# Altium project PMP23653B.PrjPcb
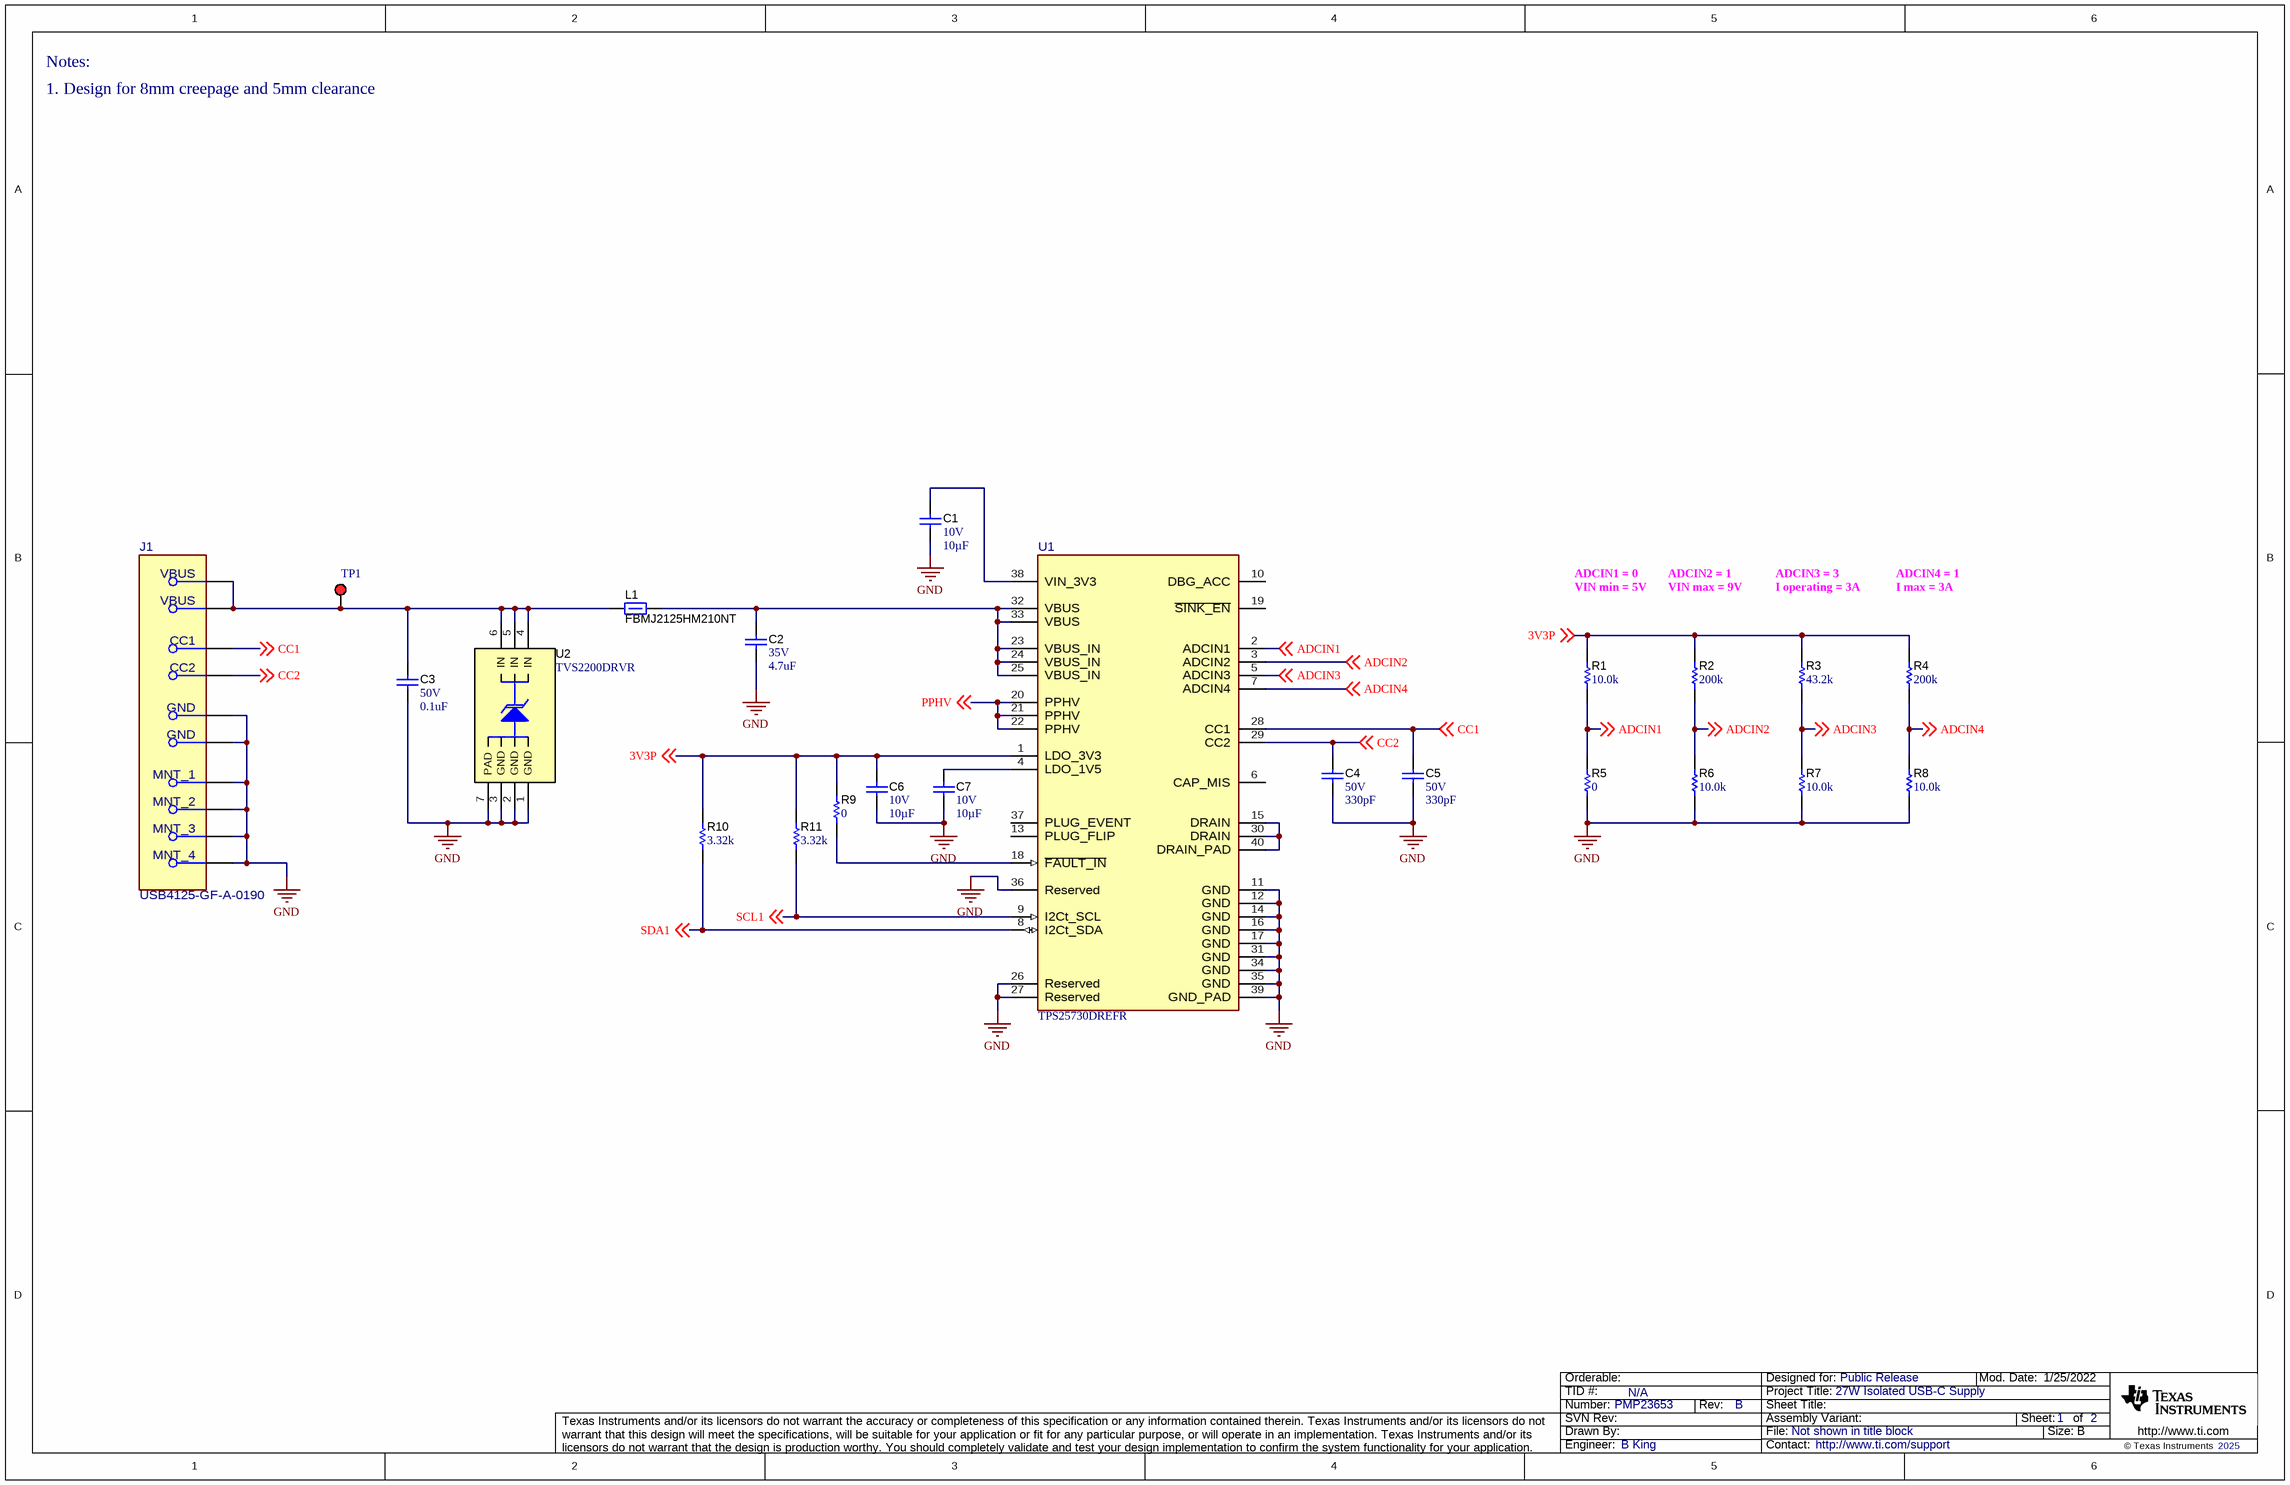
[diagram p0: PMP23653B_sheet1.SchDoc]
CopyrightYear: 2025; PCB_Layout: B King; PCB_Rev: B; PRJ_Customer: Public Release; PRJ_Engineer: B King; PRJ_Number: PMP23653; PRJ_Title: 27W Isolated USB-C Supply; SCH_Rev: B; TechSupport: http://www.ti.com/support; TID: N/A
2 sheets, 90 parts. Net scope: global (net labels, ports and power ports of the same name join across sheets).
Board file: PMP23653B.PcbDoc
Sheets:
  PMP23653B_sheet1.SchDoc
  PMP23653B_sheet2.SchDoc

## Sheet PMP23653B_sheet1.SchDoc
size 431 x 279 mm; Date: Not shown in title block; ApprovedBy: Not shown in title block; CheckedBy: Not shown in title block; Author: Not shown in title block; CompanyName: Not shown in title block; Engineer: Not shown in title block; Organization: Not shown in title block; Address1: Not shown in title block; Address2: Not shown in title block; Address3: Not shown in title block; Address4: Not shown in title block; DocumentNumber: 2; Revision: Use project parameter SCH_Rev; SheetNumber: 1; SheetTotal: 2; PageSetup: Record=PageOptions¦CenterHorizontal=True¦CenterVertical=True¦PrintScale=1.00¦XCorrection=1.00¦YCorrection=1.00¦PrintKind=0¦BorderSize=5000000¦LeftOffset=0¦BottomOffset=0¦Orientation=2¦PaperLength=1000¦PaperWidth=1000¦Scale=100¦PaperSource=15¦PrintQuality=600¦MediaType=1¦DitherType=10¦PaperKind=Letter¦PrintScaleMode=1

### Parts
C1  VDC_V: 10V  ValueDisplayed: 10µF  [0402_070]  (hidden comment: GRM155R61A106ME44)
C2  VDC_V: 35V  ValueDisplayed: 4.7uF  [0603S]  (hidden comment: GRM188R6YA475KE15D)
C3  VDC_V: 50V  ValueDisplayed: 0.1uF  [0402S]  (hidden comment: C1005X7R1H104K050BB)
C4  VDC_V: 50V  ValueDisplayed: 330pF  [0402S]  (hidden comment: GRM1555C1H331FA01J)
C5  VDC_V: 50V  ValueDisplayed: 330pF  [0402S]  (hidden comment: GRM1555C1H331FA01J)
C6  VDC_V: 10V  ValueDisplayed: 10µF  [0402_070]  (hidden comment: GRM155R61A106ME44)
C7  VDC_V: 10V  ValueDisplayed: 10µF  [0402_070]  (hidden comment: GRM155R61A106ME44)
J1  USB4125-GF-A-0190  [FP-USB4125-GF-A-0190_CONN_USB-MFG]
L1  FBMJ2125HM210NT  [0805_HV1]
R1  ValueDisplayed: 10.0k  [0402S]  (hidden comment: CRCW040210K0FKED)
R2  ValueDisplayed: 200k  [0402S]  (hidden comment: CRCW0402200KFKED)
R3  ValueDisplayed: 43.2k  [0402S]  (hidden comment: CRCW040243K2FKED)
R4  ValueDisplayed: 200k  [0402S]  (hidden comment: CRCW0402200KFKED)
R5  ValueDisplayed: 0  [0402S]  (hidden comment: CRCW04020000Z0ED)
R6  ValueDisplayed: 10.0k  [0402S]  (hidden comment: CRCW040210K0FKED)
R7  ValueDisplayed: 10.0k  [0402S]  (hidden comment: CRCW040210K0FKED)
R8  ValueDisplayed: 10.0k  [0402S]  (hidden comment: CRCW040210K0FKED)
R9  ValueDisplayed: 0  [0402S]  (hidden comment: CRCW04020000Z0ED)
R10  ValueDisplayed: 3.32k  [0402S]  (hidden comment: CRCW04023K32FKED)
R11  ValueDisplayed: 3.32k  [0402S]  (hidden comment: CRCW04023K32FKED)
TP1  5000  [Keystone5000]  (value not drawn)
U1  TPS25730DREFR  [REF0038A-MFG]
U2  TVS2200DRVR  [DRV0006A]

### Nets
GND: C1.1 C2.2 C3.2 C4.1 C5.1 C6.1 C7.1 J1.1(MNT_1) J1.2(MNT_2) J1.3(MNT_3) J1.4(MNT_4) J1.A12(GND) J1.B12(GND) R5.1 R6.2 R7.2 R8.2 U1.11(GND) U1.12(GND) U1.14(GND) U1.16(GND) U1.17(GND) U1.26(Reserved) U1.27(Reserved) U1.31(GND) U1.34(GND) U1.35(GND) U1.36(Reserved) U1.39(GND_PAD) U2.1(GND) U2.2(GND) U2.3(GND) U2.7(PAD)
3V3P: C6.2 R1.1 R2.2 R3.2 R4.2 R9.2 R10.2 R11.2 U1.1(LDO_3V3) ; off-sheet 3V3P
ADCIN1: R1.2 R5.2 U1.2(ADCIN1) ; off-sheet ADCIN1
ADCIN2: R2.1 R6.1 U1.3(ADCIN2) ; off-sheet ADCIN2
ADCIN3: R3.1 R7.1 U1.5(ADCIN3) ; off-sheet ADCIN3
ADCIN4: R4.1 R8.1 U1.7(ADCIN4) ; off-sheet ADCIN4
CC1: C5.2 J1.A5(CC1) U1.28(CC1) ; off-sheet CC1
CC2: C4.2 J1.B5(CC2) U1.29(CC2) ; off-sheet CC2
PPHV: U1.20(PPHV) U1.21(PPHV) U1.22(PPHV) ; off-sheet PPHV
SCL1: R11.1 U1.9(I2Ct_SCL) ; off-sheet SCL1
SDA1: R10.1 U1.8(I2Ct_SDA) ; off-sheet SDA1
NetC1_2: C1.2 U1.38(VIN_3V3)
NetC2_1: C2.1 L1.2 U1.23(VBUS_IN) U1.24(VBUS_IN) U1.25(VBUS_IN) U1.32(VBUS) U1.33(VBUS)
NetC3_1: C3.1 J1.A9(VBUS) J1.B9(VBUS) L1.1 TP1.1 U2.4(IN) U2.5(IN) U2.6(IN)
NetC7_2: C7.2 U1.4(LDO_1V5)
NetR9_1: R9.1 U1.18(~{FAULT_IN})
NetU1_15: U1.15(DRAIN) U1.30(DRAIN) U1.40(DRAIN_PAD)

Not connected (* = marked no-connect by the designer): U1 6(CAP_MIS) 10(DBG_ACC) 13(PLUG_FLIP) 19(~{SINK_EN}) 37(PLUG_EVENT)

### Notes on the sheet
- Notes:
- 1. Design for 8mm creepage and 5mm clearance
- ADCIN1 = 0
- VIN min = 5V
- ADCIN2 = 1
- VIN max = 9V
- ADCIN3 = 3
- I operating = 3A
- ADCIN4 = 1
- I max = 3A

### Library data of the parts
C1 C6 C7 = CMP-0074692-1: CAP, CERM, 10 µF, 10 V,+/- 20%, X5R, 0402; Manufacturer: MuRata; TaMin_C: -55°C; Polarized: N; Green_Lifecycle: Not Set; SizeAreaWB_mm2: 3.0; Green_REACh: Incomplete; U/M: EA; Value: 10uF; TaMax_C: 85°C; SizeZ_mm: 0.7; SizeX_mm: 1.0; SizeY_mm: 0.5; Cap_Case: 0402; AEC Category: Q200
C2 = CMP-0007357-5: CAP, CERM, 4.7 uF, 35 V, +/- 10%, X5R, 0603; Manufacturer: MuRata; TaMin_C: -55°C; Polarized: N; SizeAreaWB_mm2: 4.68; Value1: Unknown; U/M: EA; Value: 4.7uF; TaMax_C: 85°C; SizeZ_mm: 1; SizeX_mm: 1.6; SizeY_mm: 0.8; Cap_Case: 0603; SizeArea_mm2: 1.28; Cap_F: 4.7µF; AEC Category: Q200
C3 = CMP-0006297-2: CAP, CERM, 0.1 uF, 50 V, +/- 10%, X7R, 0402; Manufacturer: TDK; TaMin_C: -55°C; ESR_ohm: 39.064m; Polarized: N; SizeAreaWB_mm2: 3; Value1: 0.039064 ohm; U/M: EA; Value: 0.1uF; TaMax_C: 125°C; SizeZ_mm: 0.6; SizeX_mm: 1; SizeY_mm: 0.5; Cap_Case: 0402; Cap_F: 100nF; IRMS_A: 814.669mA; AEC Category: Q200
C4 C5 = CMP-0006455-2: CAP, CERM, 330 pF, 50 V, +/- 1%, C0G/NP0, 0402; Manufacturer: MuRata; TaMin_C: -55°C; Polarized: N; SizeAreaWB_mm2: 3; Value1: Unknown; U/M: EA; Value: 330pF; TaMax_C: 125°C; SizeZ_mm: 0.6; SizeX_mm: 1; SizeY_mm: 0.5; Cap_Case: 0402; AEC Category: Q200
J1 = CMP-0094557-1: 24 (6+18 Dummy) Position USB-C (USB TYPE-C) USB 2.0 Receptacle Connector; Manufacturer: GCT; Usb Standard: USB 2.0; Conn Orientation: Horizontal; SizeZ_mm: 3.51mm; ContactFinish: Gold; Current_A: 3A; Voltage_V: 20V; Is Female: yes; Shrouded: true; AEC Qualified: No
L1 = CMP-0003375-1: Ferrite Bead, 21 ohm @ 100 MHz, 6 A, 0805; Manufacturer: Taiyo Yuden; ZTyp@100MHz_Ohm: 21; SizeAreaWB_mm2: 6.75; DCR_ohm: 4m; Value1: 0.004 ohm; Value: 21 ohm; Imax_A: 6A; SizeZ_mm: 1.45; SizeX_mm: 2; SizeY_mm: 1.25; SizeArea_mm2: 2.5
R1 R6-R8 = CMP-0025958-3: RES, 10.0 k, 1%, 0.063 W, AEC-Q200 Grade 0, 0402; Manufacturer: Vishay-Dale; Power_W: 63mW; TempCo: 100 ppm/C; Value_Code: 10k0; Value: 10.0k; EIA_Code: E96; Res_ohm: 10k; SizeX_mm: 1; SizeY_mm: 0.5; SizeZ_mm: 0.6; Value2: 0.063W; AEC Qualified: Y; VDC_V: 50V; AEC Category: Q200; AEC Grade: 0
R2 R4 = CMP-0026158-2: RES, 200 k, 1%, 0.063 W, AEC-Q200 Grade 0, 0402; Manufacturer: Vishay-Dale; Power_W: 63mW; TempCo: 100 ppm/C; Value: 200k; EIA_Code: E96; SizeX_mm: 1; SizeY_mm: 0.5; SizeZ_mm: 0.6; Value2: 0.063W; AEC Qualified: Y; VDC_V: 50V; AEC Category: Q200; AEC Grade: 0
R3 = CMP-0026379-2: RES, 43.2 k, 1%, 0.063 W, AEC-Q200 Grade 0, 0402; Manufacturer: Vishay-Dale; Power_W: 63mW; TempCo: 100 ppm/C; Value_Code: 43k2; Value: 43.2k; EIA_Code: E96; SizeX_mm: 1; SizeY_mm: 0.5; SizeZ_mm: 0.6; Value2: 0.063W; AEC Qualified: Y; VDC_V: 50V; AEC Category: Q200; AEC Grade: 0
R5 R9 = CMP-0026822-3: RES, 0, 5%, 0.063 W, AEC-Q200 Grade 0, 0402; Manufacturer: Vishay-Dale; Power_W: 63mW; TempCo: 200 ppm/C; Value_Code: 0000; Value: 0; EIA_Code: E24; SizeX_mm: 1; SizeY_mm: 0.5; SizeZ_mm: 0.6; Value2: 0.063W; AEC Qualified: Y; VDC_V: 50V; AEC Category: Q200
R10 R11 = CMP-0026333-2: RES, 3.32 k, 1%, 0.063 W, AEC-Q200 Grade 0, 0402; Manufacturer: Vishay-Dale; Power_W: 63mW; TempCo: 100 ppm/C; Value_Code: 3k32; Value: 3.32k; EIA_Code: E96; SizeX_mm: 1; SizeY_mm: 0.5; SizeZ_mm: 0.6; Value2: 0.063W; AEC Qualified: Y; VDC_V: 50V; AEC Category: Q200; AEC Grade: 0
TP1 = CMP-0055137-2: Test Point, Miniature, Red, TH; Manufacturer: Keystone Electronics; Green_REACh: Passed; Green_Lifecycle: Active; ContactFinish: Silver; CNHeader: FALSE; CT: TRUE
U1 = CMP-0120752-1: Sink-only USB Type-C® and USB Power Delivery (PD) controller with no firmware development required 38-WQFN -40 to 125; Manufacturer: Texas Instruments; SizeZ_mm: 0.8mm; Interface: I2C,USB; Max Supply Voltage: 22V; Min Supply Voltage: 3V; Number Of Ports: 1; Standoff Height: 0mm; TaMax_C: +65°C; TaMin_C: -40°C; TJmax_C: +125°C; Usb Standard: USB 3.1
U2 = CMP-0077834-1: 22-V Precision Surge Protection Clamp, DRV0006A (WSON-6); Alternate Manufacturer: Texas Instruments; SizeAreaWB_mm2: 9.0; SizeZ_mm: 0.8; SizeX_mm: 2.0; SizeArea_mm2: 4.0; CompType: IC; AEC Qualified: N; AEC Category: Q200

## Sheet PMP23653B_sheet2.SchDoc
size 431 x 279 mm; Date: Not shown in title block; ApprovedBy: Not shown in title block; CheckedBy: Not shown in title block; Author: Not shown in title block; CompanyName: Not shown in title block; Engineer: Not shown in title block; Organization: Not shown in title block; Address1: Not shown in title block; Address2: Not shown in title block; Address3: Not shown in title block; Address4: Not shown in title block; DocumentNumber: 3; Revision: Use project parameter SCH_Rev; SheetNumber: 2; SheetTotal: 2; PageSetup: Record=PageOptions¦CenterHorizontal=True¦CenterVertical=True¦PrintScale=1.00¦XCorrection=1.00¦YCorrection=1.00¦PrintKind=0¦BorderSize=5000000¦LeftOffset=0¦BottomOffset=0¦Orientation=2¦PaperLength=1000¦PaperWidth=1000¦Scale=100¦PaperSource=15¦PrintQuality=600¦MediaType=1¦DitherType=10¦PaperKind=Letter¦PrintScaleMode=1
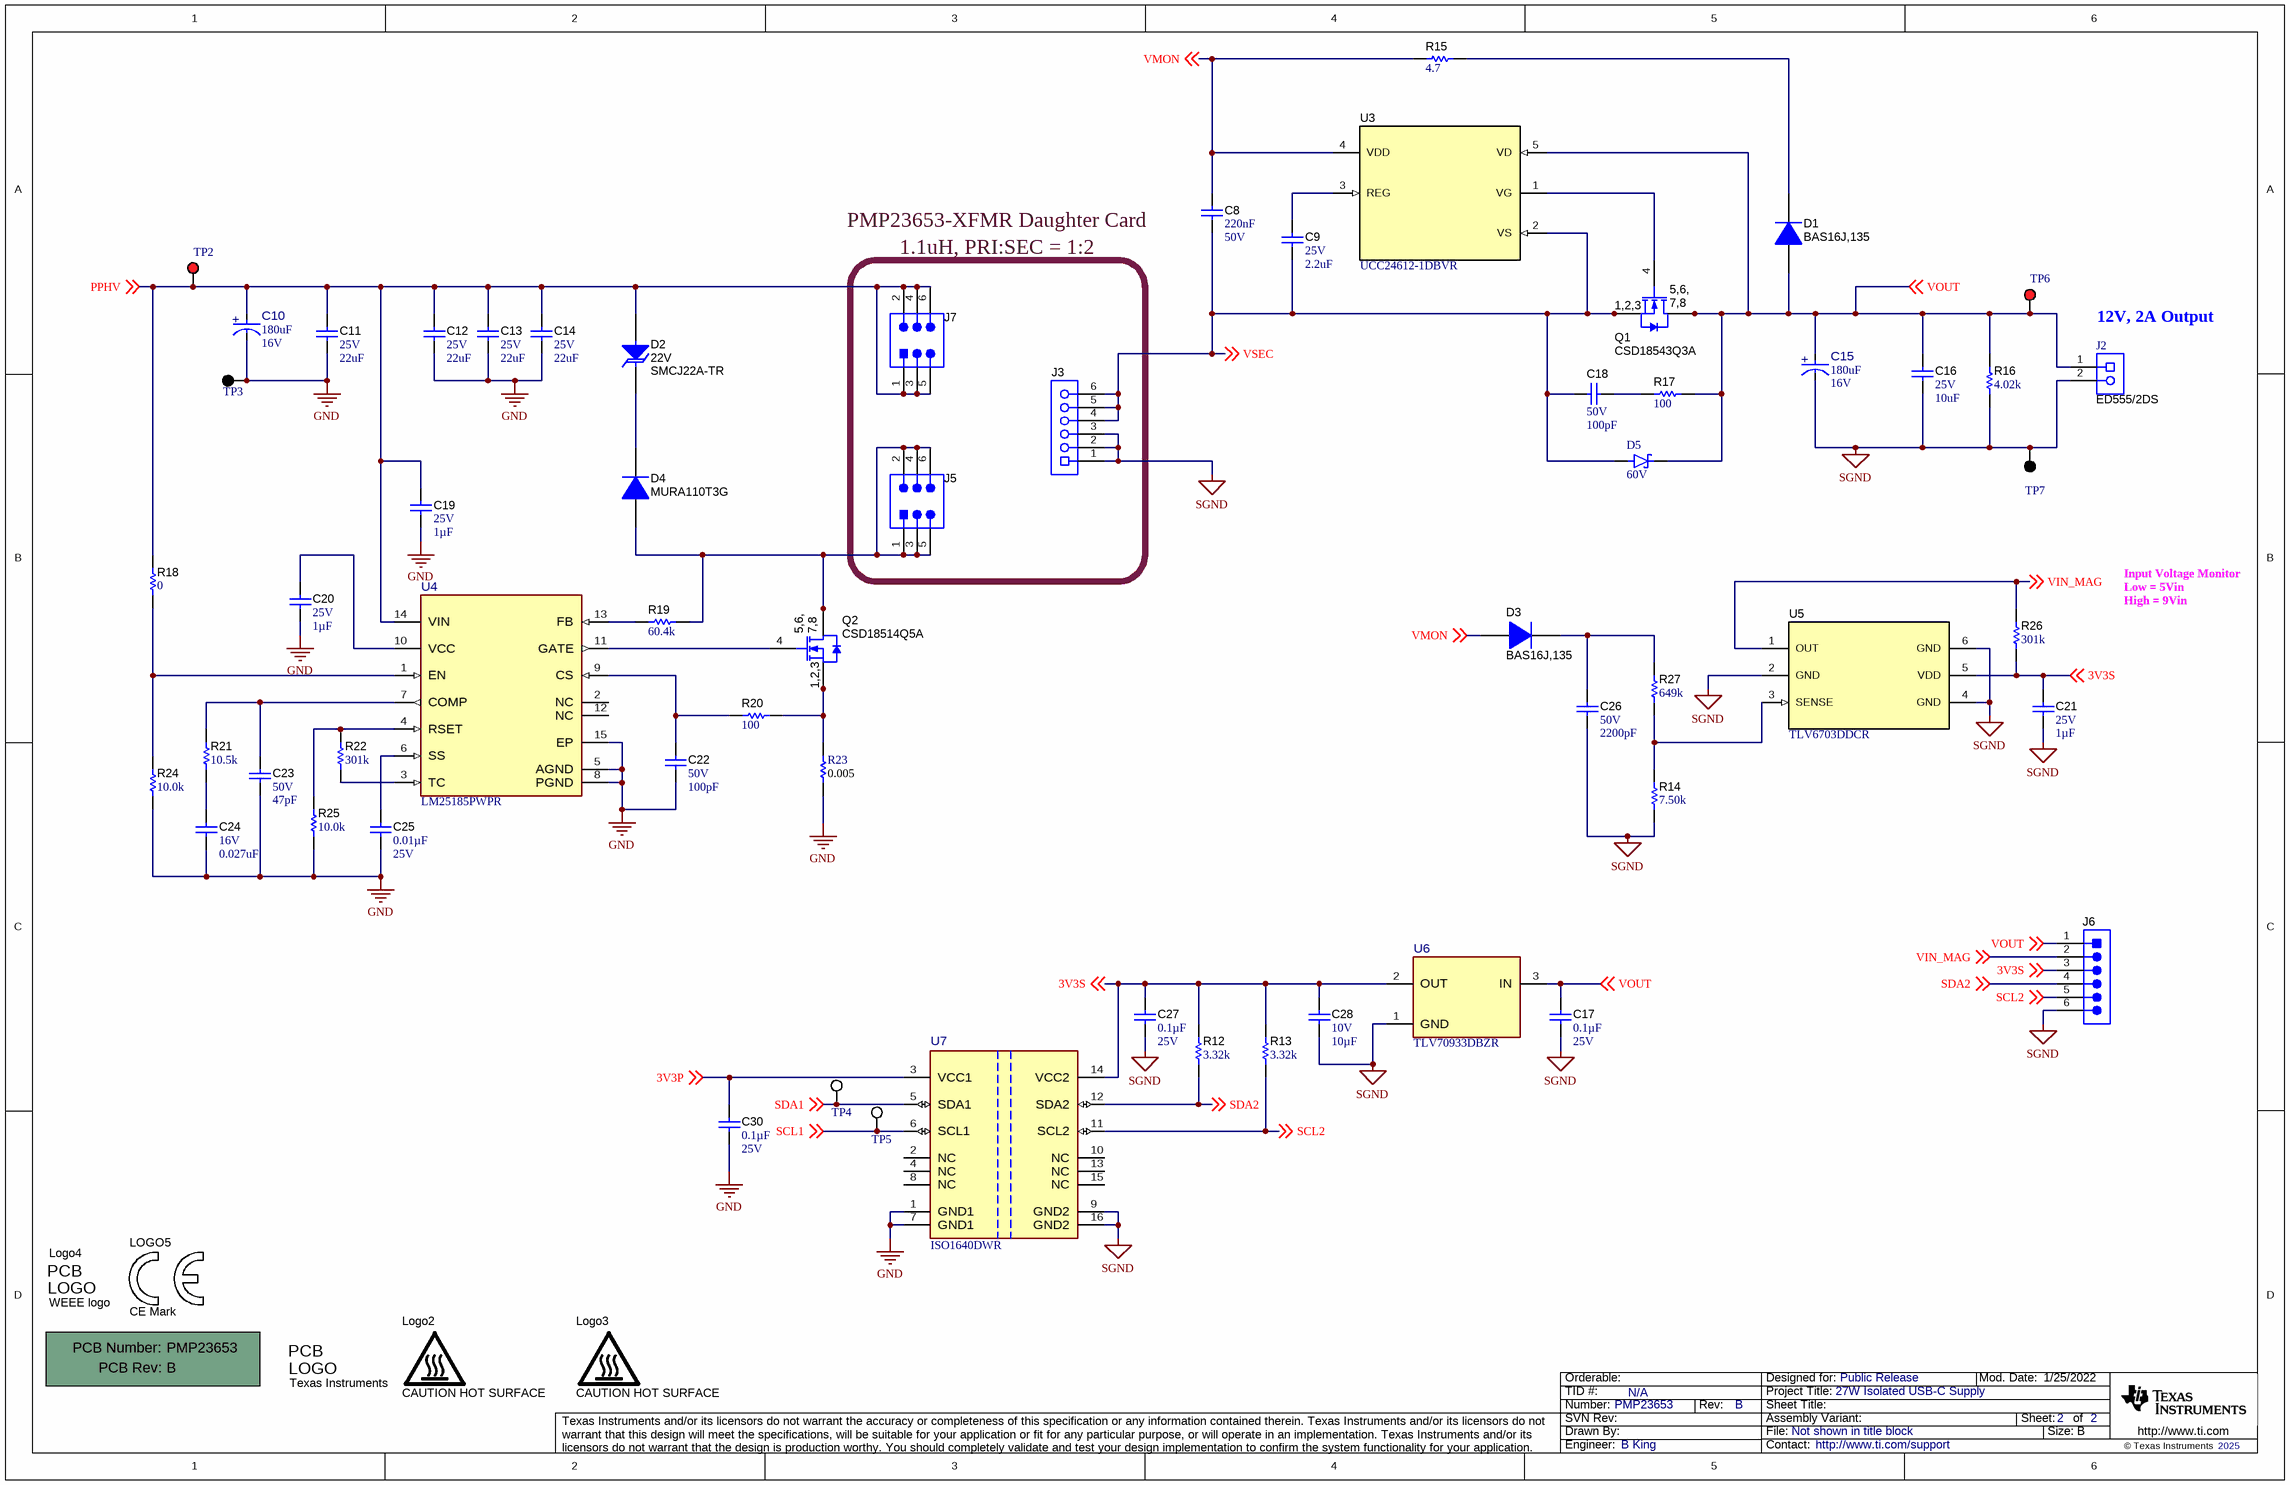
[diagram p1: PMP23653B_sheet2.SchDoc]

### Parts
!PCB  Printed Circuit Board  (value not drawn)  (mechanical)
C8  Cap_F: 220nF  VDC_V: 50V  [0603L]  (hidden comment: GRM188R71H224KAC4D)
C9  VDC_V: 25V  ValueDisplayed: 2.2uF  [0402_070]  (hidden comment: GRM155R61E225KE11D)
C10  ValueDisplayed: 180uF  VDC_V: 16V  [FP-16SEPC180MX_RADIAL-MFG]  (hidden comment: 16SEPC180MX)
C11  VDC_V: 25V  ValueDisplayed: 22uF  [0805L]  (hidden comment: GRM21BR61E226ME44L)
C12  VDC_V: 25V  ValueDisplayed: 22uF  [0805L]  (hidden comment: GRM21BR61E226ME44L)
C13  VDC_V: 25V  ValueDisplayed: 22uF  [0805L]  (hidden comment: GRM21BR61E226ME44L)
C14  VDC_V: 25V  ValueDisplayed: 22uF  [0805L]  (hidden comment: GRM21BR61E226ME44L)
C15  ValueDisplayed: 180uF  VDC_V: 16V  [FP-16SEPC180MX_RADIAL-MFG]  (hidden comment: 16SEPC180MX)
C16  VDC_V: 25V  ValueDisplayed: 10uF  [0603S]  (hidden comment: C1608X5R1E106M080AC)
C17  ValueDisplayed: 0.1µF  VDC_V: 25V  [0402S]  (hidden comment: CC0402KRX7R8BB104)
C18  VDC_V: 50V  ValueDisplayed: 100pF  [0402S]  (hidden comment: GRM1555C1H101JA01D)
C19  VDC_V: 25V  ValueDisplayed: 1µF  [0402S]  (hidden comment: GRM155R61E105MA12D)
C20  VDC_V: 25V  ValueDisplayed: 1µF  [0402S]  (hidden comment: GRM155R61E105MA12D)
C21  VDC_V: 25V  ValueDisplayed: 1µF  [0402S]  (hidden comment: GRM155R61E105MA12D)
C22  VDC_V: 50V  ValueDisplayed: 100pF  [0402S]  (hidden comment: GRM1555C1H101JA01D)
C23  VDC_V: 50V  ValueDisplayed: 47pF  [0402S]  (hidden comment: GRM1555C1H470JZ01)
C24  VDC_V: 16V  ValueDisplayed: 0.027uF  [0402S]  (hidden comment: GRM155R61C273KA01D)
C25  ValueDisplayed: 0.01µF  VDC_V: 25V  [0402S]  (hidden comment: 04023C103JAT2A)
C26  VDC_V: 50V  ValueDisplayed: 2200pF  [0402S]  (hidden comment: GRM155R71H222KA01D)
C27  ValueDisplayed: 0.1µF  VDC_V: 25V  [0402S]  (hidden comment: CC0402KRX7R8BB104)
C28  VDC_V: 10V  ValueDisplayed: 10µF  [0402_070]  (hidden comment: GRM155R61A106ME44)
C30  ValueDisplayed: 0.1µF  VDC_V: 25V  [0402S]  (hidden comment: CC0402KRX7R8BB104)
D1  BAS16J,135  [SOD-323F]
D2  SMCJ22A-TR  value 22V  [SMC]
D3  BAS16J,135  [SOD-323F]
D4  MURA110T3G  [SMA]
D5  60V  [SODFL3718X102N]
J2  ED555/2DS  [TERM_BLK_ED555-2DS]
J3  851-43-006-10-001000  [Mill-Max_851-XX-006-10-001000]  (value not drawn)
J5  GRPB032VWVN-RC  [Sullins_GRPB032VWVN-RC]  (value not drawn)
J6  GRPB061VWVN-RC  [Sullins_GRPB061VWVN-RC]  (value not drawn)
J7  GRPB032VWVN-RC  [Sullins_GRPB032VWVN-RC]  (value not drawn)
Logo1  Texas Instruments  [TI_Symbol_Overlay_Small]  (no BOM)
Logo2  CAUTION HOT SURFACE  [IEC_HotSurface_Small]  (no BOM)
Logo3  CAUTION HOT SURFACE  [IEC_HotSurface_Small]  (no BOM)
Logo4  WEEE logo  [WEEE_Minimum]  (no BOM)
LOGO5  CE Mark  [CE_Mark_3MM5]  (no BOM)
Q1  CSD18543Q3A  [DNH0008A]
Q2  CSD18514Q5A  [DQJ0008A]
R12  ValueDisplayed: 3.32k  [0402S]  (hidden comment: CRCW04023K32FKED)
R13  ValueDisplayed: 3.32k  [0402S]  (hidden comment: CRCW04023K32FKED)
R14  ValueDisplayed: 7.50k  [0402S]  (hidden comment: CRCW04027K50FKED)
R15  ValueDisplayed: 4.7  [0402S]  (hidden comment: CRCW04024R70JNED)
R16  ValueDisplayed: 4.02k  [0603]  (hidden comment: CRCW06034K02FKEA)
R17  ValueDisplayed: 100  [0805]  (hidden comment: CRCW0805100RJNEA)
R18  ValueDisplayed: 0  [0402S]  (hidden comment: CRCW04020000Z0ED)
R19  ValueDisplayed: 60.4k  [0402S]  (hidden comment: CRCW040260K4FKED)
R20  ValueDisplayed: 100  [0402S]  (hidden comment: CRCW0402100RJNED)
R21  ValueDisplayed: 10.5k  [0402S]  (hidden comment: CRCW040210K5FKED)
R22  ValueDisplayed: 301k  [0402S]  (hidden comment: CRCW0402301KFKED)
R23  value 0.005  [2010L]  (hidden comment: PMR50HZPFU5L00)
R24  ValueDisplayed: 10.0k  [0402S]  (hidden comment: CRCW040210K0FKED)
R25  ValueDisplayed: 10.0k  [0402S]  (hidden comment: CRCW040210K0FKED)
R26  ValueDisplayed: 301k  [0402S]  (hidden comment: CRCW0402301KFKED)
R27  ValueDisplayed: 649k  [0402S]  (hidden comment: CRCW0402649KFKED)
TP2  5000  [Keystone5000]  (value not drawn)
TP3  5001  [Keystone5001]  (value not drawn)
TP4  5002  [Keystone5002]  (value not drawn)
TP5  5002  [Keystone5002]  (value not drawn)
TP6  5000  [Keystone5000]  (value not drawn)
TP7  5001  [Keystone5001]  (value not drawn)
U3  UCC24612-1DBVR  [DBV0005A_N]
U4  LM25185PWPR  [PWP0014G-IPC_C]
U5  TLV6703DDCR  [DDC0006A_L]
U6  TLV70933DBZR  [DBZ0003A-MFG]
U7  ISO1640DWR  [DW0016A-IPC_C]

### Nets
GND: C10.1(CATHODE) C11.2 C12.2 C13.2 C14.2 C19.1 C20.1 C22.1 C23.2 C24.2 C25.1 C30.1 R23.1 R24.2 R25.2 TP3.1 U4.5(AGND) U4.8(PGND) U4.15(EP) U7.1(GND1) U7.7(GND1)
SGND: C15.1(CATHODE) C16.1 C17.1 C21.1 C26.2 C27.1 C28.1 J2.2 J3.1 J3.2 J3.3 J6.6 R14.1 R16.1 TP7.1 U5.2(GND) U5.4(GND) U5.6(GND) U6.1(GND) U7.9(GND2) U7.16(GND2)
3V3P: C30.2 U7.3(VCC1) ; off-sheet 3V3P
3V3S: C21.2 C27.2 C28.2 J6.3 R12.2 R13.2 R26.2 U5.5(VDD) U6.2(OUT) U7.14(VCC2) ; off-sheet 3V3S
PPHV: C10.2(ANODE) C11.1 C12.1 C13.1 C14.1 C19.2 D2.2(A) J7.1 J7.2 J7.3 J7.4 J7.5 J7.6 R18.1 TP2.1 U4.14(VIN) ; off-sheet PPHV
SCL1: TP5.1 U7.6(SCL1) ; off-sheet SCL1
SCL2: J6.5 R13.1 U7.11(SCL2) ; off-sheet SCL2
SDA1: TP4.1 U7.5(SDA1) ; off-sheet SDA1
SDA2: J6.4 R12.1 U7.12(SDA2) ; off-sheet SDA2
VIN_MAG: J6.2 R26.1 U5.1(OUT) ; off-sheet VIN_MAG
VMON: C8.1 D3.2(A) R15.1 U3.4(VDD) ; off-sheet VMON
VOUT: C15.2(ANODE) C16.2 C17.2 D1.2(A) D5.C(K) J2.1 J6.1 Q1.5(D) Q1.6(D) Q1.7(D) Q1.8(D) Q1.9(D) R16.2 R17.2 TP6.1 U3.5(VD) U6.3(IN) ; off-sheet VOUT
VSEC: C8.2 C9.2 C18.2 D5.A J3.4 J3.5 J3.6 Q1.1(S) Q1.2(S) Q1.3(S) U3.2(VS) ; off-sheet VSEC
NetC9_1: C9.1 U3.3(REG)
NetC18_1: C18.1 R17.1
NetC20_2: C20.2 U4.10(VCC)
NetC22_2: C22.2 R20.1 U4.9(CS)
NetC23_1: C23.1 R21.1 U4.7(COMP)
NetC24_1: C24.1 R21.2
NetC25_2: C25.2 U4.6(SS)
NetC26_1: C26.1 D3.1(K) R27.2
NetD1_1: D1.1(K) R15.2
NetD2_1: D2.1(K) D4.1(K)
NetD4_2: D4.2(A) J5.1 J5.2 J5.3 J5.4 J5.5 J5.6 Q2.5(D) Q2.6(D) Q2.7(D) Q2.8(D) Q2.9(D) R19.2
NetQ1_4: Q1.4(G) U3.1(VG)
NetQ2_1: Q2.1(S) Q2.2(S) Q2.3(S) R20.2 R23.2
NetQ2_4: Q2.4(G) U4.11(GATE)
NetR14_2: R14.2 R27.1 U5.3(SENSE)
NetR18_2: R18.2 R24.1 U4.1(EN)
NetR19_1: R19.1 U4.13(FB)
NetR22_1: R22.1 R25.1 U4.4(RSET)
NetR22_2: R22.2 U4.3(TC)

Not connected (* = marked no-connect by the designer): U4 2(NC) 12(NC); U7 2(NC) 4(NC) 8(NC) 10(NC) 13(NC) 15(NC)

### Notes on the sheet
- PMP23653-XFMR Daughter Card
- 1.1uH, PRI:SEC = 1:2
- (near J2) 12V, 2A Output
- Input Voltage Monitor
- Low = 5Vin
- High = 9Vin

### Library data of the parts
!PCB = CMP-0003618-2: Manufacturer: Any; PartNumber: PMP23653
C8 = CMP-0007445-4: CAP, CERM, 0.22 uF, 50 V, +/- 10%, X7R, 0603; Manufacturer: MuRata; TaMin_C: -55°C; Polarized: N; SizeAreaWB_mm2: 4.68; Value1: Unknown; U/M: EA; Value: 0.22uF; TaMax_C: 125°C; SizeZ_mm: 1; SizeX_mm: 1.6; SizeY_mm: 0.8; Cap_Case: 0603; SizeArea_mm2: 1.28; AEC Category: Q200
C9 = CMP-0006610-2: CAP, CERM, 2.2 uF, 25 V, +/- 10%, X5R, 0402; Manufacturer: MuRata; TaMin_C: -55°C; Polarized: N; SizeAreaWB_mm2: 3; Value1: Unknown; U/M: EA; Value: 2.2uF; TaMax_C: 85°C; SizeZ_mm: 0.7; SizeX_mm: 1; SizeY_mm: 0.5; Cap_Case: 0402; Cap_F: 2.2µF; AEC Category: Q200
C10 C15 = CMP-0089787-1: 180µF 16V Aluminum - Polymer Capacitors Radial, Can 10mOhm 5000 Hrs @ 105°C; Manufacturer: Panasonic; Tolerance_%: 20%; Esr: 10m; SizeZ_mm: 9mm; AEC Qualified: No; Leakage Current: 576uA; Life: 5000Hours; IRMS_A: 5A; Dissipation Factor: 10%
C11-C14 = CMP-0008305-2: CAP, CERM, 22 uF, 25 V, +/- 20%, X5R, 0805; Manufacturer: MuRata; TaMin_C: -55°C; Polarized: N; SizeAreaWB_mm2: 6.75; Value1: Unknown; U/M: EA; Value: 22uF; TaMax_C: 85°C; SizeZ_mm: 1.45; SizeX_mm: 2; SizeY_mm: 1.25; Cap_Case: 0805; SizeArea_mm2: 2.5; Cap_F: 22µF; AEC Category: Q200
C16 = CMP-0007007-5: CAP, CERM, 10 uF, 25 V, +/- 20%, X5R, 0603; Manufacturer: TDK; TaMin_C: -55°C; ESR_ohm: 4.639m; Polarized: N; SizeAreaWB_mm2: 4.68; Value1: 0.004639 ohm; U/M: EA; Value: 10uF; TaMax_C: 85°C; SizeZ_mm: 1; SizeX_mm: 1.6; SizeY_mm: 0.8; Cap_Case: 0603; SizeArea_mm2: 1.28; Cap_F: 10µF; IRMS_A: 2.4141A; AEC Category: Q200
C17 C27 C30 = CMP-0860555-1: CAP, CERM, 0.1 µF, 25 V,+/- 10%, X7R, 0402; Manufacturer: Yageo; SizeArea_mm2: 0.5; Cap_Case: 0402; AEC Qualified: N; SizeX_mm: 1; U/M: EA; Value: 0.1uF; TaMin_C: -55°C; SizeZ_mm: 0.6; Cap_F: 100nF; TaMax_C: 125°C; SizeAreaWB_mm2: 3; AEC Category: Q200
C18 C22 = CMP-0006410-2: CAP, CERM, 100 pF, 50 V, +/- 5%, C0G/NP0, 0402; Manufacturer: MuRata; TaMin_C: -55°C; Polarized: N; SizeAreaWB_mm2: 3; Value1: Unknown; U/M: EA; Value: 100pF; TaMax_C: 125°C; SizeZ_mm: 0.6; SizeX_mm: 1; SizeY_mm: 0.5; Cap_Case: 0402; AEC Category: Q200
C19-C21 = CMP-0078625-1: CAP, CERM, 1 µF, 25 V,+/- 20%, X5R, 0402; Manufacturer: MuRata; SizeAreaWB_mm2: 3; SizeArea_mm2: 0.5; AEC Qualified: N; AEC Category: Q200; Value: 1uF; TaMax_C: 85°C; SizeZ_mm: 0.6; TaMin_C: -55°C; U/M: EA; SizeX_mm: 1; Cap_Case: 0402
C23 = CMP-0006469-2: CAP, CERM, 47 pF, 50 V, +/- 5%, C0G/NP0, 0402; Manufacturer: MuRata; TaMin_C: -55°C; ESR_ohm: 45m; Polarized: N; SizeAreaWB_mm2: 3; Value1: 0.045 ohm; U/M: EA; Value: 47pF; TaMax_C: 125°C; SizeZ_mm: 0.6; SizeX_mm: 1; SizeY_mm: 0.5; Cap_Case: 0402; AEC Category: Q200
C24 = CMP-0006595-2: CAP, CERM, 0.027 uF, 16 V, +/- 10%, X5R, 0402; Manufacturer: MuRata; TaMin_C: -55°C; Polarized: N; SizeAreaWB_mm2: 3; Value1: Unknown; U/M: EA; TaMax_C: 85°C; SizeZ_mm: 0.6; SizeX_mm: 1; SizeY_mm: 0.5; Cap_Case: 0402; Cap_F: 27nF; AEC Category: Q200
C25 = CMP-0085568-1: CAP, CERM, 0.01 µF, 25 V,+/- 5%, X7R, 0402; Manufacturer: AVX; AEC Category: Q200; SizeAreaWB_mm2: 3; SizeArea_mm2: 0.5; Polarized: N; TaMin_C: -55°C; Value: 0.01uF; U/M: EA; SizeX_mm: 1; Cap_Case: 0402; Cap_F: 10nF; SizeZ_mm: 0.6; TaMax_C: 125°C
C26 = CMP-0006683-2: CAP, CERM, 2200 pF, 50 V, +/- 10%, X7R, 0402; Manufacturer: MuRata; TaMin_C: -55°C; Polarized: N; SizeAreaWB_mm2: 3; Value1: Unknown; U/M: EA; Value: 2200pF; TaMax_C: 125°C; SizeZ_mm: 0.6; SizeX_mm: 1; SizeY_mm: 0.5; Cap_Case: 0402; Cap_F: 2.2nF; AEC Category: Q200
C28 = CMP-0074692-1: as C1 on sheet PMP23653B_sheet1
D1 D3 = CMP-0076955-2: Diode, Switching, 100 V, 0.25 A, SOD-323F; Manufacturer: Nexperia; Vr_V: 100V; Io_A: 250mA; SizeY_mm: 1.25; AEC Category: Q101; Value1: 0.25A; Green_Lifecycle: Not Set; SizeArea_mm2: 3.125; SizeX_mm: 2.5; Value: 100V; TJmax_C: 150°C; SizeAreaWB_mm2: 7.875; SizeZ_mm: 0.8; Green_REACh: Incomplete
D2 = CMP-0085427-1: Diode, TVS, Uni, 22 V, 35.5 Vc, 1500 W, 44 A, SMC; Manufacturer: STMicroelectronics; AEC Qualified: N; Ipp: 44A; AEC Category: Q101; Value1: 35.5V; Vbr_Min: 24.4V; SizeX_mm: 8.13; Ppk: 1.5kW; SizeY_mm: 6.22; SizeArea_mm2: 50.5686; RJA_CperW: 90; SizeAreaWB_mm2: 83.2686; SizeZ_mm: 2.62
D4 = CMP-0029196-2: Diode, Ultrafast, 100 V, 2 A, SMA; Manufacturer: ON Semiconductor; SizeX_mm: 5.59; TJmax_C: 175°C; SizeAreaWB_mm2: 37.3428; Io_A: 2A; Green_REACh: Passed; SizeY_mm: 2.92; Value: 100V; Green_Lifecycle: Active; AEC Qualified: N; SizeArea_mm2: 16.3228; AEC Category: Q101; SizeZ_mm: 2.87
D5 = TSSW3U60: DIODE SCHOTTKY 60V 3A SOD123W; Manufacturer: Taiwan Semiconductor Corporation; MF: {'manufacturer': u'Taiwan Semiconductor Corporation'}
J2 = CMP-0074913-1: Terminal Block, 3.5mm Pitch, 2x1, TH; Manufacturer: On-Shore Technology; Cert_VDE: Y; CNHeader: False; Current_A: 6A; Green_Lifecycle: Active; Shrouded: N; Gender: Female; Green_REACh: Passed; Voltage_V: 150V; Row_Count: 1; Pitch_mm: 3.5; ContactFinish: Brass; CT: True
J3 = CMP-0055069-1: Receptacle, 50mil, 6x1, Gold, TH; Manufacturer: Mill-Max; CT: TRUE; Green_REACh: Passed; CompType: Socket Strip; CNHeader: FALSE; Green_Lifecycle: Active
J5 J7 = CMP-0054557-2: Header, 50mil, 3x2, Gold, TH; Manufacturer: Sullins Connector Solutions; Green_Lifecycle: Not Set; Green_REACh: Incomplete
J6 = CMP-0054561-1: Header, 50mil, 6x1, Gold,  TH; Manufacturer: Sullins Connector Solutions; CT: FALSE; CNHeader: TRUE
Logo1 = CMP-0074838-1: Texas Instrument Corporate Signature; SymbolCreator: a0412235; Lib Reference: TI_Logo; Library Reference: Logo
Logo2 Logo3 = CMP-0074837-2: IEC 61010-1 Hot Surface Warning; Manufacturer: Texas Instruments; CompType: IC; AEC Category: Q200; SymbolCreator: a0412235
Logo4 = CMP-0074769-4: Manufacturer: Texas Instruments; CompType: IC; AEC Category: Q200
LOGO5 = CMP-0074844-2: Manufacturer: Texas Instruments; SymbolCreator: a0412235; AEC Category: Q200; CompType: IC
Q1 = CMP-0000826-2: MOSFET, N-CH, 60 V, 35 A, DNH0008A (VSONP-8); Alternate Manufacturer: None; Manufacturer: Texas Instruments; SizeZ_mm: 0.9; ChType: N; Value2: 11.1 nC; Value1: 0.01; VdsMax_V: 60V; SizeX_mm: 3.3; SizeAreaWB_mm2: 18.49; Vgs_V: 20V; QgTyp_nC: 11.1; Value: 60V; Rdson45_ohm: 12m; SizeArea_mm2: 10.89; AEC Category: Q101; IdsMax_A: 35A; ChMode: Enhancement
Q2 = CMP-0000715-1: MOSFET, N-CH, 40 V, 50 A, DQJ0008A (VSONP-8); Alternate Manufacturer: None; Manufacturer: Texas Instruments; SizeZ_mm: 1.1; ChType: N; Value2: 29 nC; Value1: 0.007; VdsMax_V: 40V; SizeX_mm: 6; SizeY_mm: 4.9; Vgs_V: 20V; Value: 40V; Rdson45_ohm: 7.9m; SizeArea_mm2: 29.4; AEC Category: Q101; IdsMax_A: 50A; SizeAreaWB_mm2: 55.2; U/M: EA; QgTyp_nC: 29
R12 R13 = CMP-0026333-2: as R10 on sheet PMP23653B_sheet1
R14 = CMP-0026555-2: RES, 7.50 k, 1%, 0.063 W, AEC-Q200 Grade 0, 0402; Manufacturer: Vishay-Dale; Power_W: 63mW; TempCo: 100 ppm/C; Value_Code: 7k50; Value: 7.50k; EIA_Code: E96; Res_ohm: 7.5k; SizeX_mm: 1; SizeY_mm: 0.5; SizeZ_mm: 0.6; Value2: 0.063W; AEC Qualified: Y; VDC_V: 50V; AEC Category: Q200; AEC Grade: 0
R15 = CMP-0026942-3: RES, 4.7, 5%, 0.063 W, AEC-Q200 Grade 0, 0402; Manufacturer: Vishay-Dale; Power_W: 63mW; TempCo: 200 ppm/C; Value_Code: 4R70; Value: 4.7; EIA_Code: E24; SizeX_mm: 1; SizeY_mm: 0.5; SizeZ_mm: 0.6; Value2: 0.063W; AEC Qualified: Y; VDC_V: 50V; AEC Category: Q200; AEC Grade: 0
R16 = CMP-0022449-4: RES, 4.02 k, 1%, 0.1 W, AEC-Q200 Grade 0, 0603; Manufacturer: Vishay-Dale; Power_W: 100mW; TempCo: 100 ppm/C; Value_Code: 4k02; Value: 4.02k; EIA_Code: E96; SizeX_mm: 1.6; SizeY_mm: 0.8; SizeZ_mm: 1; Value2: 0.1W; SizeArea_mm2: 1.28; AEC Qualified: Y; VDC_V: 75V; AEC Category: Q200; AEC Grade: 0
R17 = CMP-0020445-3: RES, 100, 5%, 0.125 W, AEC-Q200 Grade 0, 0805; Manufacturer: Vishay-Dale; Power_W: 125mW; TempCo: 200 ppm/C; Value_Code: 100R; Value: 100; EIA_Code: E24; SizeX_mm: 2; SizeY_mm: 1.25; SizeZ_mm: 1.45; Value2: 0.125W; SizeArea_mm2: 2.5; AEC Qualified: Y; VDC_V: 150V; AEC Category: Q200; AEC Grade: 0
R18 = CMP-0026822-3: as R5 on sheet PMP23653B_sheet1
R19 = CMP-0026486-2: RES, 60.4 k, 1%, 0.063 W, AEC-Q200 Grade 0, 0402; Manufacturer: Vishay-Dale; Power_W: 63mW; TempCo: 100 ppm/C; Value_Code: 60k4; Value: 60.4k; EIA_Code: E96; SizeX_mm: 1; SizeY_mm: 0.5; SizeZ_mm: 0.6; Value2: 0.063W; AEC Qualified: Y; VDC_V: 50V; AEC Category: Q200; AEC Grade: 0
R20 = CMP-0026824-3: RES, 100, 5%, 0.063 W, AEC-Q200 Grade 0, 0402; Manufacturer: Vishay-Dale; Power_W: 63mW; TempCo: 200 ppm/C; Value_Code: 100R; Value: 100; EIA_Code: E24; SizeX_mm: 1; SizeY_mm: 0.5; SizeZ_mm: 0.6; Value2: 0.063W; AEC Qualified: Y; VDC_V: 50V; AEC Category: Q200; AEC Grade: 0
R21 = CMP-0025960-3: RES, 10.5 k, 1%, 0.063 W, AEC-Q200 Grade 0, 0402; Manufacturer: Vishay-Dale; Power_W: 63mW; TempCo: 100 ppm/C; Value_Code: 10k5; Value: 10.5k; EIA_Code: E96; SizeX_mm: 1; SizeY_mm: 0.5; SizeZ_mm: 0.6; Value2: 0.063W; AEC Qualified: Y; VDC_V: 50V; AEC Category: Q200; AEC Grade: 0
R22 R26 = CMP-0026280-2: RES, 301 k, 1%, 0.063 W, AEC-Q200 Grade 0, 0402; Manufacturer: Vishay-Dale; Power_W: 63mW; TempCo: 100 ppm/C; Value: 301k; EIA_Code: E96; SizeX_mm: 1; SizeY_mm: 0.5; SizeZ_mm: 0.6; Value2: 0.063W; AEC Qualified: Y; VDC_V: 50V; AEC Category: Q200; AEC Grade: 0
R23 = PMR50HZPFU5L00: RES 0.005 OHM 1% 1W 2010; Manufacturer_Name: ROHM Semiconductor
R24 R25 = CMP-0025958-3: as R1 on sheet PMP23653B_sheet1
R27 = CMP-0026496-2: RES, 649 k, 1%, 0.063 W, AEC-Q200 Grade 0, 0402; Manufacturer: Vishay-Dale; Power_W: 63mW; TempCo: 100 ppm/C; Value: 649k; EIA_Code: E96; SizeX_mm: 1; SizeY_mm: 0.5; SizeZ_mm: 0.6; Value2: 0.063W; AEC Qualified: Y; VDC_V: 50V; AEC Category: Q200; AEC Grade: 0
TP2 TP6 = CMP-0055137-2: as TP1 on sheet PMP23653B_sheet1
TP3 TP7 = CMP-0055138-2: Test Point, Miniature, Black, TH; Manufacturer: Keystone Electronics; ContactFinish: Silver; CNHeader: FALSE; Green_Lifecycle: Active; Green_REACh: Passed; CT: TRUE
TP4 TP5 = CMP-0055139-2: Test Point, Miniature, White, TH; Manufacturer: Keystone Electronics; ContactFinish: Silver; Green_REACh: Passed; CT: TRUE; Green_Lifecycle: Active; CNHeader: FALSE
U3 = CMP-0013050-3: High-Frequency Multi-Mode Synchronous Rectifier Controller, DBV0005A (SOT-23-5); Manufacturer: Texas Instruments; Alternate PartNumber: UCC24612-1DBVT; SizeX_mm: 2.8; SizeY_mm: 2.9; CompType: IC; SizeZ_mm: 1.45; SizeArea_mm2: 8.12; SizeAreaWB_mm2: 14.82; AEC Category: Q200; AEC Qualified: N
U4 = CMP-0123130-1: 42-VIN primary side regulation flyback controller with low IQ and low EMI; Manufacturer: Texas Instruments; SizeZ_mm: 1.2mm; AEC Qualified: No; Max Supply Voltage: 42V; Min Supply Voltage: 4.5V; Nominal Supply Current: 25-425uA; Number Of Outputs: 1; Standoff Height: 0.05mm; Switching Frequency: 11-350kHz; TJmax_C: +150°C
U5 = CMP-0084583-1: High Voltage Comparator with Integrated Reference, DDC0006A (SOT-23-THIN-6); Alternate Manufacturer: Texas Instruments; Alternate PartNumber: TLV6703DDCT; SizeZ_mm: 0.87; SizeY_mm: 2.95; Rating: Catalog; SizeArea_mm2: 4.8675; AEC Qualified: N; SizeAreaWB_mm2: 10.4675; AEC Category: Q200; SizeX_mm: 1.65; CompType: IC
U6 = CMP-0127088-1: 150-mA 30-V low-dropout (LDO) linear regulator with 3.2-μA supply current 3-SOT-23 -40 to 125; Manufacturer: Texas Instruments; SizeZ_mm: 1.12mm; AEC Qualified: No; Accuracy Percentage: 2%; Dropout Voltage: 1000mV; Max Supply Voltage: 30V; Min Supply Voltage: 4.3V; Nominal Supply Current: 3.2uA; Number Of Outputs: 1; Output Type: Fixed; Output Voltage: 3.3V; Standoff Height: 0.01mm; TJmax_C: +125°C
U7 = CMP-0095765-1: I²C Digital Isolator 5000Vrms 2 Channel - 50kV/µs CMTI 16-SOIC (0.295", 7.50mm Width); Manufacturer: Texas Instruments; Max Supply Voltage: 5.5V; TJmax_C: +150°C; Min Supply Voltage: 2.25V; Interface: I2C,SMBus; TaMin_C: -40°C; SizeZ_mm: 2.65mm; Standoff Height: 0.1mm; AEC Qualified: No; TaMax_C: +125°C

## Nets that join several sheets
GND: PMP23653B_sheet1 (33 pins), PMP23653B_sheet2 (21 pins)
3V3P: PMP23653B_sheet1 (9 pins), PMP23653B_sheet2 (C30.2 U7.3)
PPHV: PMP23653B_sheet1 (U1.20 U1.21 U1.22), PMP23653B_sheet2 (16 pins)
SCL1: PMP23653B_sheet1 (R11.1 U1.9), PMP23653B_sheet2 (TP5.1 U7.6)
SDA1: PMP23653B_sheet1 (R10.1 U1.8), PMP23653B_sheet2 (TP4.1 U7.5)

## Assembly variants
001: not fitted J3 J5 J7 R1 R16 R22 R24 TP4 TP5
